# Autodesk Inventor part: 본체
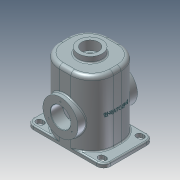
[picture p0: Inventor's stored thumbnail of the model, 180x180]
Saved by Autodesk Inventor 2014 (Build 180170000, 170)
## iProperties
Company: 한국ATC센터
Created: 2014-10
Part Number: 본체
Document SubType Name: Modeling
Designer: 한국ATC센터
Density: 1 g/cm^3
Material: 일반
Mass: 1088.52 g
Surface Area: 2150.09 cm^2
Volume: 1088.52 cm^3
Appearance: 청회색(연함)
Author: KYOUNG IL JANG
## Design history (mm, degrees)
sketch "스케치1"
  geometry: L1 (-70, 65)-(70, 65); L2 (70, 65)-(70, -65); L3 (70, -65)-(-70, -65); L4 (-70, -65)-(-70, 65); 3 further points
  constraints: 8 end point, 2 midpoint, 2 parallel, 1 horizontal, 1 horizontal alignment, 1 perpendicular, 1 vertical alignment
  dimensions: "d0" = 140 distance of L2.end L3.end; "d68" = 130 distance of L3.end L1.start
extrude "돌출1" new body sketch "스케치1" distance "d1" = 180; taper "d2" = 0 deg
fillet "모깎기1" dims "d3" = 55
feature "쉘1" dims "d4" = 10
sketch "스케치2"
  geometry: L1 (-70, 10)-(-70, -10) reference; L2 (-15, -65)-(-82, -65); L3 (-82, 65)-(-15, 65); L4 (-83, 57)-(-78, 57); L5 (-78, 41)-(-83, 41); L6 (-100, 47)-(-100, -47); A1 r 55 centre (-15, 10) between (-15, 65) and (-70, 10) reference; A2 r 55 centre (-15, -10) between (-70, -10) and (-15, -65) reference; A3 r 8 centre (-78, 49) between (-78, 41) and (-78, 57); A4 r 8 centre (-83, 49) between (-83, 57) and (-83, 41); A5 r 18 centre (-82, 47) between (-82, 65) and (-100, 47); A6 r 18 centre (-82, -47) between (-100, -47) and (-82, -65); 1 further point
  constraints: 10 end point, 9 tangent, 8 point on circle, 4 centre point, 2 parallel, 2 perpendicular, 1 equal radius
  dimensions: "d6" = 49 vertical distance of point (0, 0) A3.centre; "d8" = 16 distance between parallel lines of L4 L5; "d64" = 18 radius of A5; "d65" = 8 distance from line of A3.centre L1; "d66" = 30 distance between parallel lines of L6 L1; "d67" = 5 distance of A4.centre A3.centre
extrude "돌출2" join sketch "스케치2" distance "d9" = 10; taper "d10" = 0 deg
extrude "돌출3" cut sketch "스케치2" stored distance "d11" = 10; taper "d12" = 0 deg
sketch "스케치3"
  geometry: L1 (-65, 10)-(-65, 180) reference; L2 (-55, 0)-(-55, 170) reference; L3 (-77, 75)-(-45, 75); L4 (10, 0)-(-10, 0) reference; L5 (-77, 75)-(-77, 120.5); L6 (-77, 120.5)-(-55, 120.5); L7 (-55, 120.5)-(-45, 110.5); L8 (-45, 110.5)-(-45, 75); 3 further points
  constraints: 10 end point, 4 perpendicular, 1 point on line
  dimensions: "d13" = 75 distance between parallel lines of L3 L4; "d14" = 12 distance from line of L1 L3.start; "d15" = 10 distance from line of L3.end L2; "d16" = 91 diameter of L6 L3; "d17" = 135 deg angle of L7 L2
revolve "회전1" sketch "스케치3" stored, may be unused: angle "d18" = 90 deg
sketch "스케치4"
  geometry: C1 r 45.5 at (0, 0) reference; 2 further points
  constraints: 1 vertical alignment
  dimensions: "d19" = 35 distance of C1.centre point (0, 35)
hole "구멍1" sketch "스케치4" at (0, 35) diameter "d20" = 3.459; stored, may be unused: countersink angle "d24" = 90 deg, drill point angle "d26" = 118 deg; dims "d21" = 13, "d22" = 4, "d23" = 2, "d25" = 16
fillet "모깎기2" dims "d30" = 3
hole "구멍2" diameter "d33" = 52; stored, may be unused: countersink angle "d37" = 90 deg, drill point angle "d39" = 118 deg; dims "d31" = 10, "d32" = 10, "d34" = 13, "d35" = 4, "d36" = 2, "d38" = 16
sketch "스케치5"
  geometry: C1 r 31 at (0, 0); 1 further point
  constraints: 1 centre point, 1 coincident
  dimensions: "d40" = 62 diameter of C1
extrude "돌출4" join sketch "스케치5" distance "d41" = 15; taper "d42" = 0 deg
hole "구멍3" diameter "d45" = 43; stored, may be unused: countersink angle "d49" = 90 deg, drill point angle "d51" = 118 deg; dims "d43" = 10, "d44" = 10, "d46" = 13, "d47" = 4, "d48" = 2, "d50" = 16
fillet "모깎기3" dims "d52" = 3
fillet "모깎기4" dims "d53" = 3
chamfer "모따기1" distance "d55" = 1; stored, may be unused: second distance "d56" = 2, angle "d57" = 45 deg
sketch "스케치6"
  geometry: 2 further points
  constraints: 1 vertical alignment, 1 other
  dimensions: "d71" = 90 distance of point (0, 0) point (0, 90)
feature "엠보싱2" sketch "스케치6" dims "d0" = 140, "d68" = 130, "d72" = 1, "d73" = 0
fillet "모깎기6" dims "d74" = 10
sketch "스케치7"
  geometry: C1 r 15 at (0, 0); C2 r 21.5 at (0, 0) reference; C3 r 25 at (0, 0); 1 further point
  constraints: 2 centre point, 2 coincident
  dimensions: "d61" = 30 diameter of C1; "d75" = 50 diameter of C3
extrude "돌출5" join sketch "스케치7" distance "d62" = 10; taper "d63" = 0 deg
feature "면 이동1" dims "d76" = 1
node "솔리드1"
mirror "대칭1"
mirror "대칭2"
pattern_circular "원형 패턴1" dims angle "d28" = 360 deg
mirror "대칭3"
